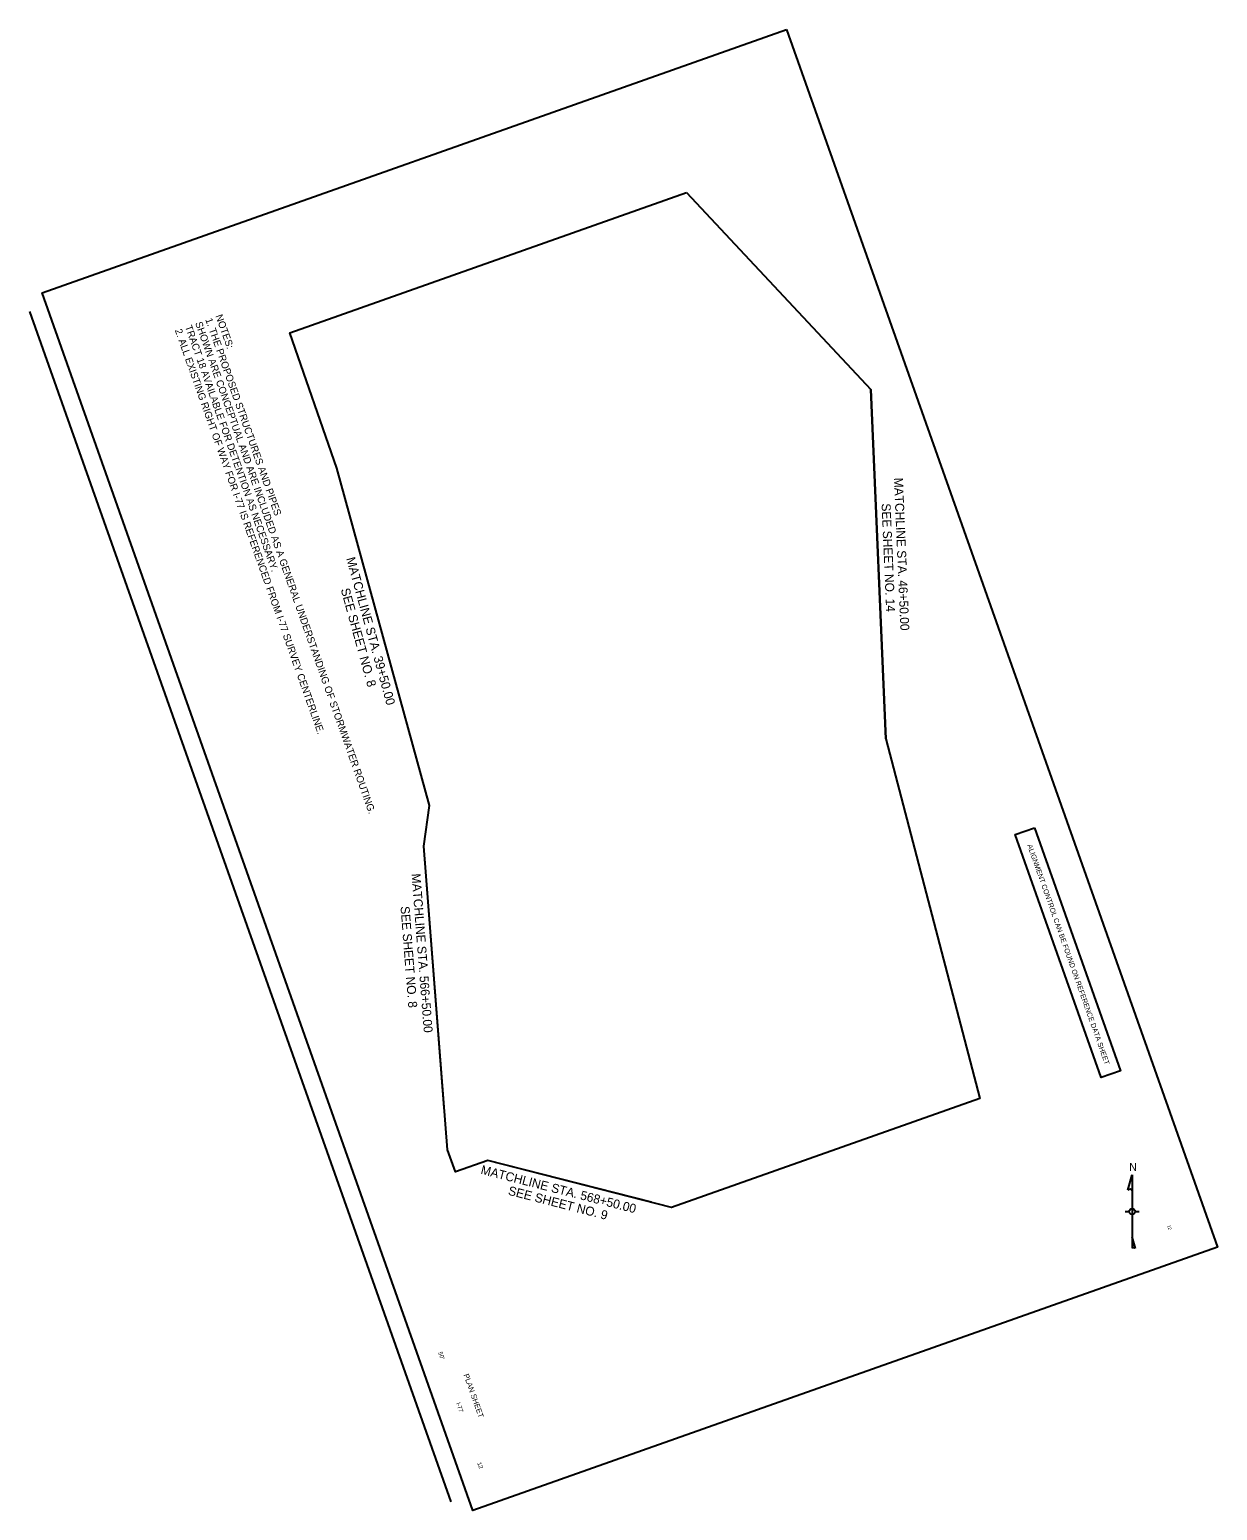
# Model space of a CAD drawing. Extents: x 2005793 to 2007447, y 1135965 to 1138029.
import ezdxf

# ---------------------------------------------------------------- set-up
doc = ezdxf.new("R2010")
doc.units = 0
for name, color, linetype in [('North Arrow', 7, 'Continuous'), ('RD_SHT_IplotShp', 7, 'Continuous'), ('RD_SHT_MatchLine', 7, 'Continuous'), ('RD_SHT_Misc1', 7, 'Continuous'), ('RD_SHT_ShtClip', 7, 'Continuous'), ('RD_SHT_TX', 7, 'Continuous')]:
    doc.layers.add(name, color=color, linetype=linetype)

msp = doc.modelspace()

# ---------------------------------------------------------------- linework, layer by layer
at = {"layer": 'North Arrow'}
for p, q in [((2007322.7, 1136411.5), (2007328.6, 1136432.5)), ((2007328.6, 1136432.5), (2007328.6, 1136410.3)), ((2007328.6, 1136432.5), (2007328.6, 1136330.3)), ((2007318.9, 1136381.4), (2007324.6, 1136381.4)), ((2007332.6, 1136381.4), (2007338.3, 1136381.4)), ((2007328.6, 1136346.1), (2007328.6, 1136330.3)), ((2007333.2, 1136330), (2007328.6, 1136346.1))]:
    msp.add_line(p, q, dxfattribs=at)
msp.add_circle((2007328.6, 1136381.4), 4.02, dxfattribs=at)
for centre, radius, start, end in [((2007325.3, 1136409), 3.59, 22.3707, 136.1387), ((2007330.8, 1136327.8), 3.3, 43.3397, 130.5607)]:
    msp.add_arc(centre, radius, start, end, dxfattribs=at)
at = {"layer": 'RD_SHT_IplotShp'}
msp.add_lwpolyline([(2006847, 1138028.8), (2007447.3, 1136331.8), (2006410.3, 1135965), (2005810, 1137661.9)], close=True, dxfattribs=at)
at = {"layer": 'RD_SHT_MatchLine'}
for p, q in [((2006985.3, 1137040.4), (2006964.4, 1137527.4)), ((2006349.9, 1136947.4), (2006220.5, 1137417.4)), ((2006370.2, 1136526.2), (2006341.8, 1136890.8)), ((2006659.1, 1136394.4), (2006431, 1136452.8))]:
    msp.add_line(p, q, dxfattribs=at)
at = {"layer": 'RD_SHT_ShtClip'}
msp.add_lwpolyline([(2006707.7, 1137801.6), (2006964.4, 1137527.4), (2006985.3, 1137040.4), (2007116.6, 1136539.2), (2006687, 1136387.3), (2006431, 1136452.8), (2006385.9, 1136436.9), (2006374.8, 1136467.3), (2006341.8, 1136890.8), (2006349.9, 1136947.4), (2006220.5, 1137417.4), (2006155.1, 1137606.1)], close=True, dxfattribs=at)
at = {"layer": 'RD_SHT_TX'}
msp.add_line((2005792.6, 1137636), (2006379.6, 1135976.8), dxfattribs=at)
msp.add_lwpolyline([(2007192.5, 1136916.4), (2007312.3, 1136577.8), (2007285.5, 1136568.4), (2007165.7, 1136906.9)], close=True, dxfattribs=at)

# ---------------------------------------------------------------- texts
at = {"layer": 'North Arrow'}
msp.add_text('N', height=11.1, dxfattribs=at).set_placement((2007324.5, 1136438))
at = {"layer": 'RD_SHT_MatchLine'}
for s, rotation, p in [('MATCHLINE STA. 46+50.00', 272.4547, (2006996.7, 1137404)), ('SEE SHEET NO. 14', 272.4547, (2006979.5, 1137368.2)), ('MATCHLINE STA. 39+50.00', 285.3889, (2006233.6, 1137291.7)), ('SEE SHEET NO. 8', 285.3889, (2006226, 1137248.5)), ('MATCHLINE STA. 566+50.00', 274.4504, (2006324.6, 1136852.1)), ('SEE SHEET NO. 8', 274.4504, (2006309.3, 1136806.6)), ('MATCHLINE STA. 568+50.00', 345.6281, (2006420.2, 1136434.2)), ('SEE SHEET NO. 9', 345.6281, (2006458.4, 1136405.1))]:
    msp.add_text(s, height=12.5, rotation=rotation, dxfattribs=at).set_placement(p)
at = {"layer": 'RD_SHT_Misc1'}
for s, p in [('NOTES:', (2006051.4, 1137629.8)), ('2. ALL EXISTING RIGHT OF WAY FOR I-77 IS REFERENCED FROM I-77 SURVEY CENTERLINE.', (2005994.8, 1137609.8)), ('TRACT 18 AVAILABLE FOR DETENTION AS NECESSARY. ', (2006008.9, 1137614.8)), ('SHOWN ARE CONCEPTUAL AND ARE INCLUDED AS A GENERAL UNDERSTANDING OF STORMWATER ROUTING.  ', (2006023.1, 1137619.8)), ('1. THE PROPOSED STRUCTURES AND PIPES ', (2006037.2, 1137624.8))]:
    msp.add_text(s, height=10, rotation=289.482, dxfattribs=at).set_placement(p)
at = {"layer": 'RD_SHT_TX'}
for s, height, p in [('ALIGNMENT CONTROL CAN BE FOUND ON REFERENCE DATA SHEET', 7, (2007182.4, 1136891.8)), ('12', 4.5, (2007377.3, 1136361.8)), ("50'", 6, (2006361.7, 1136184.9)), ('PLAN SHEET', 7.5, (2006397, 1136153.9)), ('I-77', 6, (2006386.7, 1136114.3)), ('12', 6, (2006416.1, 1136031))]:
    msp.add_text(s, height=height, rotation=289.482, dxfattribs=at).set_placement(p)

doc.saveas('drawing.dxf')
